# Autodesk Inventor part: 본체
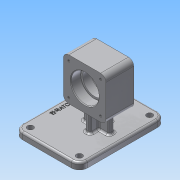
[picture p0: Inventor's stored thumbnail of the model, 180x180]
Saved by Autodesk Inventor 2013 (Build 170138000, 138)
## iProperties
Created: 2020-11
Part Number: 본체
Material: 알루미늄 6061
Document SubType Name: Modeling
Designer: Administrator
Density: 2.71 g/cm^3
Mass: 685.029 g
Surface Area: 544.461 cm^2
Volume: 252.778 cm^3
Author: Administrator
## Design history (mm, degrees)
sketch "스케치1"
  geometry: L1 (-65, 49)-(65, 49); L2 (65, 49)-(65, -49); L3 (65, -49)-(-65, -49); L4 (-65, -49)-(-65, 49); L5 (-65, 49)-(65, -49); L6 (65, 49)-(-65, -49); 1 further point
  constraints: 12 end point, 2 midpoint, 2 parallel, 1 horizontal, 1 perpendicular
  dimensions: "d0" = 130 distance of L1.start L1.end; "d2" = 98 distance of L1.end L2.end
extrude "돌출1" new body sketch "스케치1" distance "d3" = 10; taper "d4" = 0 deg
sketch "스케치2"
  geometry: L1 (-45, 102)-(19, 102); L2 (19, 102)-(19, 38); L3 (19, 38)-(-45, 38); L4 (-45, 38)-(-45, 102); L5 (-45, 102)-(19, 38); L6 (19, 102)-(-45, 38); L7 (-49, 0)-(49, 0) reference; L8 (49, 10)-(-49, 10) reference; 2 further points
  constraints: 12 end point, 2 midpoint, 2 parallel, 1 horizontal, 1 perpendicular
  dimensions: "d5" = 64 distance of L1.end L2.end; "d7" = 64 distance of L1.start L1.end; "d8" = 62 horizontal distance of L8.start point (-13, 70); "d9" = 70 distance from line of L7 point (-13, 70)
extrude "돌출2" join sketch "스케치2" stored distance "d10" = 42; taper "d11" = 0 deg
sketch "스케치3"
  geometry: L1 (-17, -9)-(17, -9); L2 (17, -9)-(17, -17); L3 (17, -17)-(-17, -17); L4 (-17, -17)-(-17, -9); L5 (-17, -9)-(17, -17); L6 (17, -9)-(-17, -17); L7 (-65, 49)-(65, 49) reference; L8 (65, -49)-(-65, -49) reference; L9 (65, 49)-(65, -49) reference; 2 further points
  constraints: 12 end point, 2 midpoint, 2 parallel, 1 horizontal, 1 perpendicular
  dimensions: "d12" = 8 distance of L1.end L2.end; "d14" = 62 distance from line of L7 point (0, -13); "d15" = 65 distance from line of point (0, -13) L9; "d16" = 34 distance of L2.end L3.end
extrude "돌출3" join sketch "스케치3" stored distance "d17" = 42; taper "d18" = 0 deg
sketch "스케치4"
  geometry: L1 (4, -33)-(-4, -33); L2 (-4, -33)-(-4, 7); L3 (-4, 7)-(4, 7); L4 (4, 7)-(4, -33); L5 (4, -33)-(-4, 7); L6 (-4, -33)-(4, 7); L7 (65, -49)-(-65, -49) reference; L8 (-65, 49)-(65, 49) reference; 2 further points
  constraints: 12 end point, 2 midpoint, 2 parallel, 1 horizontal, 1 perpendicular
  dimensions: "d19" = 8 distance of L2.end L3.end; "d21" = 65 horizontal distance of L8.end point (0, -13); "d22" = 62 distance from line of point (0, -13) L8; "d23" = 40 distance of L3.end L1.start
extrude "돌출4" join sketch "스케치4" stored distance "d24" = 42; taper "d25" = 0 deg
sketch "스케치5"
  geometry: L1 (102, -45)-(102, 19) reference; L2 (38, -45)-(102, -45) reference; 4 further points
  constraints: 2 midpoint, 1 horizontal alignment, 1 vertical alignment
hole "구멍1" sketch "스케치5" at (70, -13) diameter "d26" = 36; stored, may be unused: countersink angle "d30" = 90 deg, drill point angle "d32" = 0 deg; dims "d27" = 6, "d28" = 42, "d29" = 15, "d31" = 27
sketch "스케치6"
  geometry: L1 (-102, 19)-(-102, -45) reference; L2 (-38, 19)-(-102, 19) reference; 4 further points
  constraints: 2 midpoint, 1 horizontal alignment, 1 vertical alignment
hole "구멍2" sketch "스케치6" at (-70, -13) diameter "d33" = 42; stored, may be unused: countersink angle "d37" = 90 deg, drill point angle "d39" = 0 deg; dims "d34" = 6, "d35" = 4, "d36" = 2, "d38" = 15
fillet "모깎기1" dims "d48" = 8
sketch "스케치8"
  geometry: L1 (65, 49)-(-65, 49) reference; L2 (65, -49)-(65, 49) reference; 2 further points
  constraints: 1 other
  dimensions: "d49" = 65 distance from line of L2 point (0, 39); "d50" = 10 distance from line of point (0, 39) L1
feature "엠보싱1" sketch "스케치8" dims "d0" = 130, "d2" = 98, "d51" = 0.5, "d52" = 0
fillet "모깎기2" dims "d53" = 12
hole "구멍3" diameter "d56" = 9; stored, may be unused: countersink angle "d60" = 90 deg, drill point angle "d62" = 0 deg; dims "d54" = 10, "d55" = 10, "d57" = 6, "d58" = 4, "d59" = 2, "d61" = 15
hole "구멍4" diameter "d65" = 9; stored, may be unused: countersink angle "d69" = 90 deg, drill point angle "d71" = 0 deg; dims "d63" = 10, "d64" = 10, "d66" = 6, "d67" = 4, "d68" = 2, "d70" = 15
hole "구멍5" diameter "d74" = 9; stored, may be unused: countersink angle "d78" = 90 deg, drill point angle "d80" = 0 deg; dims "d72" = 10, "d73" = 10, "d75" = 6, "d76" = 4, "d77" = 2, "d79" = 15
hole "구멍6" diameter "d83" = 9; stored, may be unused: countersink angle "d87" = 90 deg, drill point angle "d89" = 0 deg; dims "d81" = 10, "d82" = 10, "d84" = 6, "d85" = 4, "d86" = 2, "d88" = 15
hole "구멍7" diameter "d92" = 3.242; stored, may be unused: countersink angle "d96" = 90 deg, drill point angle "d98" = 118 deg; dims "d90" = 10, "d91" = 10, "d93" = 8, "d94" = 4, "d95" = 2, "d97" = 10
hole "구멍8" diameter "d101" = 3.242; stored, may be unused: countersink angle "d105" = 90 deg, drill point angle "d107" = 118 deg; dims "d99" = 10, "d100" = 10, "d102" = 8, "d103" = 4, "d104" = 2, "d106" = 10
hole "구멍9" diameter "d110" = 3.242; stored, may be unused: countersink angle "d114" = 90 deg, drill point angle "d116" = 118 deg; dims "d108" = 10, "d109" = 10, "d111" = 8, "d112" = 4, "d113" = 2, "d115" = 10
hole "구멍10" diameter "d119" = 3.242; stored, may be unused: countersink angle "d123" = 90 deg, drill point angle "d125" = 118 deg; dims "d117" = 10, "d118" = 10, "d120" = 8, "d121" = 4, "d122" = 2, "d124" = 10
hole "구멍11" diameter "d128" = 3.242; stored, may be unused: countersink angle "d132" = 90 deg, drill point angle "d134" = 118 deg; dims "d126" = 10, "d127" = 10, "d129" = 8, "d130" = 4, "d131" = 2, "d133" = 10
hole "구멍12" diameter "d137" = 3.242; stored, may be unused: countersink angle "d141" = 90 deg, drill point angle "d143" = 118 deg; dims "d135" = 10, "d136" = 10, "d138" = 8, "d139" = 4, "d140" = 2, "d142" = 10
hole "구멍13" diameter "d146" = 3.242; stored, may be unused: countersink angle "d150" = 90 deg, drill point angle "d152" = 118 deg; dims "d144" = 10, "d145" = 10, "d147" = 8, "d148" = 4, "d149" = 2, "d151" = 10
hole "구멍14" diameter "d155" = 3.242; stored, may be unused: countersink angle "d159" = 90 deg, drill point angle "d161" = 118 deg; dims "d153" = 10, "d154" = 10, "d156" = 8, "d157" = 4, "d158" = 2, "d160" = 10
fillet "모깎기3" dims "d162" = 3
fillet "모깎기4" dims "d163" = 3
fillet "모깎기5" dims "d164" = 3
fillet "모깎기6" dims "d165" = 3
fillet "모깎기7" dims "d166" = 0.3
chamfer "모따기1" distance "d167" = 1; stored, may be unused: second distance "d168" = 2, angle "d169" = 45 deg
node "솔리드1"
